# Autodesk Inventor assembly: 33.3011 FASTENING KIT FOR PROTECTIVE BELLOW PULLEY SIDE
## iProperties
Created: 2007-06
Part Number: 33.3011 FASTENING KIT FOR PROTECTIVE BELLOW PULLEY SIDE
Document SubType Name: Assembly
Designer: Andy Moles
Author: Andy Moles
